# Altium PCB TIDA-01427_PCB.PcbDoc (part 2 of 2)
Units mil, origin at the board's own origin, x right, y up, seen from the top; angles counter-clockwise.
Board outline 1968.5 x 3149.61 mil, 4 copper layers (Top Layer, GND, PWR, Bottom Layer), stack 61.6 mil thick; 174 components, 73 nets, 411 pads, 102 vias.
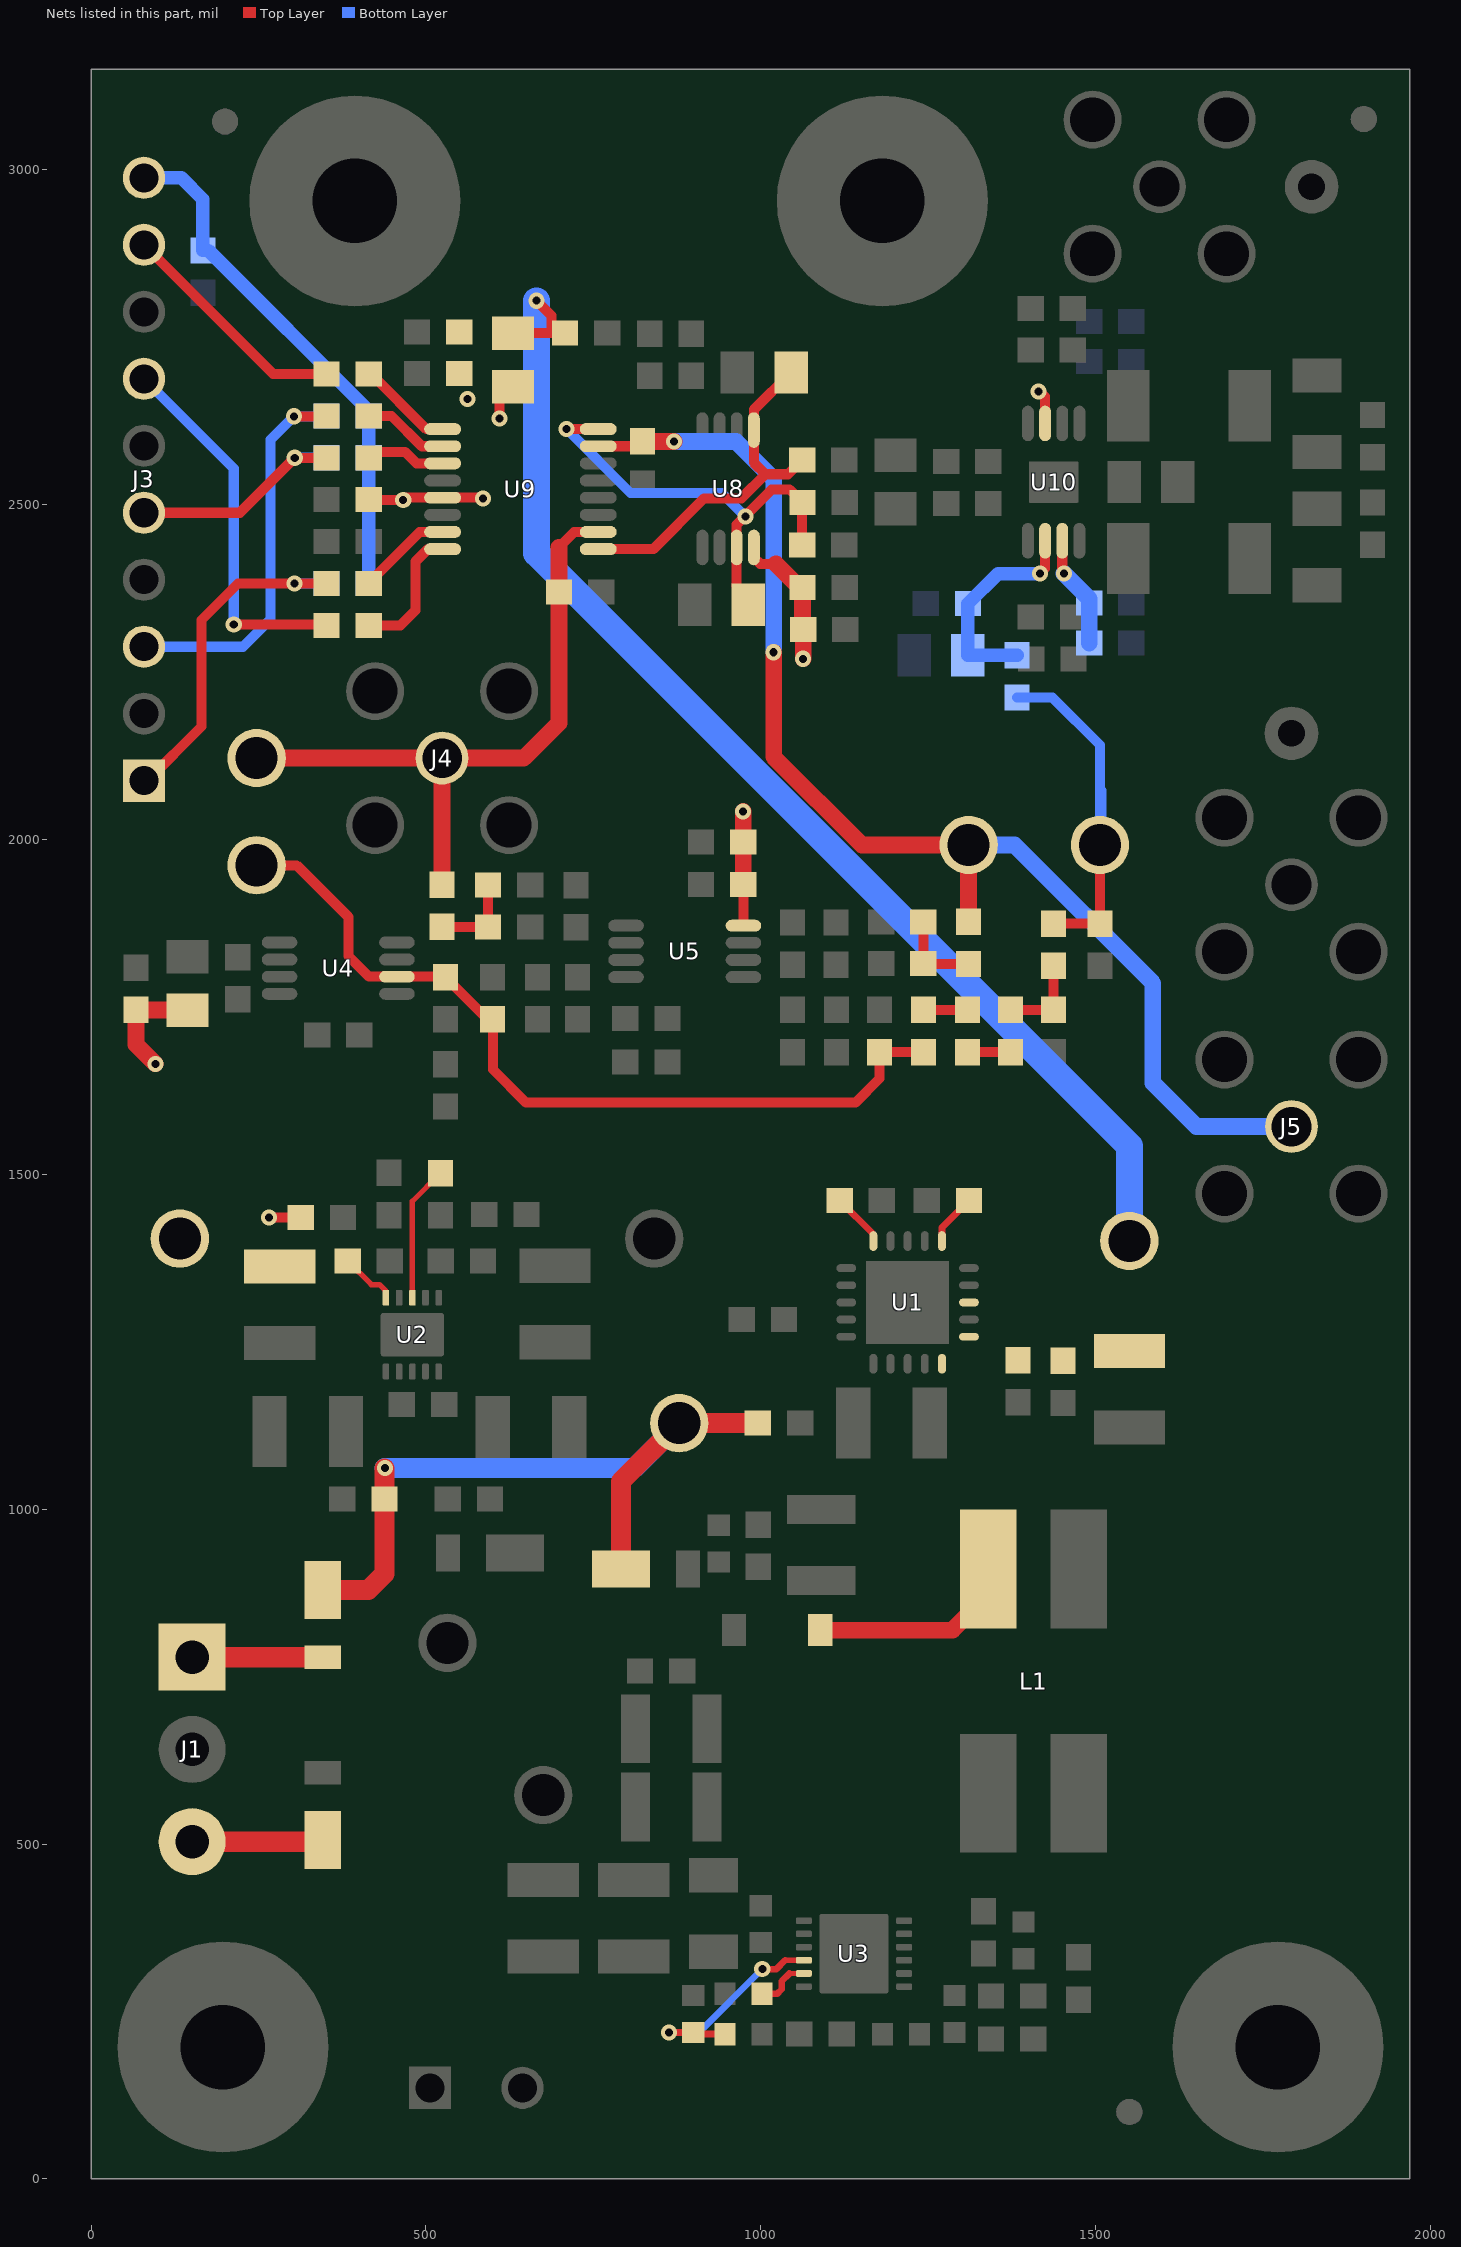
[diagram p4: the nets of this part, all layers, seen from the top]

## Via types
v1: diameter 24, hole 12, Top Layer to Bottom Layer, tented both sides, 80 vias
v2: diameter 19.68, hole 7.87, Top Layer to Bottom Layer, 19 vias
v3: diameter 24, hole 12, Top Layer to Bottom Layer, 3 vias

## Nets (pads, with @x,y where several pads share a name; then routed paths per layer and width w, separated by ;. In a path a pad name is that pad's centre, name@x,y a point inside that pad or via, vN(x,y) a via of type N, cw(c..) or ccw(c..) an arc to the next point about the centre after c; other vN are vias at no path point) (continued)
NetC76_1: C76.1 C77.1 R53.2 U10.2 | length 329.5
  Top Layer w15: v1(1416.5,2396.49) 1424.2,2404.19 U10.2@1424.2,2445.4
  Bottom Layer w20: R53.2@1382.52,2274.5 C76.1@1308.5,2274.49 1309,2274.99 C77.1@1309,2351.49 1354,2396.49 v1(1416.5,2396.49)
NetD1_2: D1.2 J1.1 | length 209.1
  Top Layer w30: J1.1@136.9,779.1 137.2,778.8 D1.2@345.9,778.8
NetD2_1: D2.1 J1.3 | length 195.9
  Top Layer w30: J1.3@151,503.41 343.5,503.41 D2.1@345.9,505.8
NetD3_2: D3.2 L1.4 | length 311
  Top Layer w25: D3.2@1088.47,819.26 1286.26,819.26 1339.38,872.38 L1.4@1339.38,910.45
NetJ3_1: J3.1 R45.1 R59.1 | length 530.7
  Top Layer w15: J3.1@84,2087.26 165,2168.26 165,2327.26 219.5,2381.76 R45.1@351.5,2381.76
  Bottom Layer w15: v1(303.43,2381.83) R59.1@351.5,2381.83
NetJ3_3: J3.3 R43.1 R58.1 | length 620.9
  Top Layer w15: v1(303,2631.26) 351,2631.26 R43.1@351.5,2631.76
  Bottom Layer w15: J3.3@79,2287.26 227,2287.26 268,2328.26 268,2596.26 v1(303,2631.26) 350.94,2631.26 R58.1@351.5,2631.83
NetJ3_5: J3.5 R40.1 R57.1 | length 354
  Top Layer w15: J3.5@79,2487.26 222,2487.26 v1(304.07,2569.33) 304.13,2569.26 R40.1@351.5,2569.26
  Bottom Layer w15: v1(304.07,2569.33) R57.1@351.5,2569.33
NetJ3_7: J3.7 R39.1 | length 562.3
  Top Layer w15: v1(213,2320.26) 348.5,2320.26 350.5,2318.26 R39.1@351.5,2319.26
  Bottom Layer w15: J3.7@79,2687.26 213,2553.26 v1(213,2320.26)
NetJ3_9: J3.9 R37.1 | length 352.4
  Top Layer w15: J3.9@79,2887.26 272,2694.26 R37.1@351.5,2694.26
NetR2_2: R2.2 U1.6 | length 77.3
  Top Layer w10: U1.6@1270.18,1399.99 1270.18,1420.31 R2.2@1310.5,1460.62
NetR3_2: R3.2 U1.10 | length 81.5
  Top Layer w10: R3.2@1117.5,1460.62 1167.82,1410.31 U1.10@1167.82,1399.99
NetR8_2: R8.2 U3.5 | length 82.3
  Top Layer w8: 1042.47,306.73 U3.5@1064.09,306.73
  Top Layer w10: R8.2@1001.46,276.26 1024,276.26 1031,283.26 1031,295.26 1042.47,306.73
NetR9_1: R9.1 R14.2 U3.4 | length 327.7
  Top Layer w8: 1036.16,326.42 U3.4@1064.09,326.42
  Top Layer w10: v1(862.44,218.7) R9.1@898.9,218.7 ; R9.1@901.34,216.26 R14.2@946.34,216.26 ; v1(1002,313.26) 1023,313.26 1036.16,326.42
  Bottom Layer w10: v1(862.44,218.7) 907.44,218.7 v1(1002,313.26)
NetR16_1: R16.1 U2.8 | length 203.4
  Top Layer w8: U2.8@479.58,1315.48 479.58,1459.5 R16.1@521.58,1501.5
NetR17_2: R17.2 R22.2 R23.1 | length 129.7
  Top Layer w15: R22.2@1242.5,1876.09 R17.2@1242.5,1814.09 1242.99,1813.6 R23.1@1310,1813.6
NetR18_2: R18.2 R20.2 R21.1 | length 131.7
  Top Layer w15: R21.1@524,1869.14 592,1869.14 R18.2@592.5,1868.64 R20.2@592.5,1931.64
NetR29_1: R29.1 R56.2 | length 64.2
  Top Layer w15: R29.1@1308.38,1682.14 R56.2@1372.62,1682.14
NetR29_2: R29.2 R54.1 | length 64.4
  Top Layer w15: R54.1@1244,1745.13 R29.2@1308.38,1745.13
NetR31_1: R31.1 R33.2 R56.1 | length 130.1
  Top Layer w15: R56.1@1372.62,1745.13 R33.2@1437,1745.13 R31.1@1437,1810.88
NetR37_2: R37.2 U9.9 | length 144.4
  Top Layer w15: R37.2@414.5,2694.26 418.35,2694.26 500.52,2612.09 U9.9@524.86,2612.09
NetR39_2: R39.2 U9.16 | length 200.2
  Top Layer w15: R39.2@414.5,2319.26 462,2319.26 484,2341.26 484,2414.26 502.7,2432.96 U9.16@524.86,2432.96
NetR40_2: R40.2 U9.11 | length 121.3
  Top Layer w15: R40.2@414.5,2569.26 423.5,2578.26 468.71,2578.26 486.06,2560.91 U9.11@524.86,2560.91
NetR43_2: R43.2 U9.10 | length 129.1
  Top Layer w15: R43.2@414.5,2631.76 448.5,2631.76 493.76,2586.5 U9.10@524.86,2586.5
NetR45_2: R45.2 U9.15 | length 142.5
  Top Layer w15: R45.2@414.5,2381.76 414.5,2382.41 490.64,2458.55 U9.15@524.86,2458.55
P5V: C2.1 C3.1 C4.1 C43.1 L4.2 P5V.1 U1.1 U1.3 U1.20 | length 1905.4
  Top Layer w15: L4.2@610,2755.26 L4.2@630,2755.26 687.5,2755.26 687.5,2781.33 v1(665.07,2803.76)
  Bottom Layer w40: v1(665.07,2803.76) 665.07,2426.93 1550,1542 P5V.1@1550,1400.26
P13V: C6.2 C7.1 C29.1 C30.1 C31.2 C56.1 C57.2 C61.1 C63.2 L2.2 P13V.1 R4.2 U2.10 U5.8 U8.8 U10.3 U10.7 | length 908.6
  Top Layer w8: R4.2@383.09,1370.36 418.45,1335 430.58,1335 440.21,1325.37 U2.10@440.21,1315.48
  Top Layer w15: L2.2@143.5,1745.14 L2.2@144,1744.64 ; v1(265.58,1435.36) C6.2@313.09,1435.36 ; C31.2@973.5,1932.64 973.86,1932.27 U5.8@973.86,1870.88 ; U8.8@989.39,2435.42 989.39,2420.61 999,2411 1022,2411 ; C57.2@1062.01,2313.76 C57.2@1063.01,2312.76 ; v1(1414.5,2668.49) 1416.5,2668.49 1424.2,2660.79 U10.7@1424.2,2620.6 ; U10.3@1449.8,2445.4 1449.8,2399.2 v1(1452.5,2396.49)
  Top Layer w25: v1(96,1664.64) 67,1693.64 C30.1@67,1745.14 L2.2@143.5,1745.14 ; C31.2@973.5,1932.64 C29.1@973.5,1995.64 v1(973.5,2041.13) ; 1022,2411 1022.31,2411 1057.55,2375.76 C56.1@1062.01,2375.76 C57.2@1062.01,2313.76 ; v1(1063.01,2269.26) C57.2@1063.01,2312.76
  Bottom Layer w25: v1(1452.5,2396.49) 1490.01,2358.99 C61.1@1490.01,2292.76
P15V_EXT: D1.1 D4.1 P15V.1 R1.2 R6.2 | length 1105.1
  Top Layer w30: D1.1@335.9,865.61 D1.1@335.9,872.5 ; D1.1@345.9,879.2 413.74,879.2 437.99,903.45 R6.2@437.99,1015 v1@437.99,1060.5 ; D4.1@790.8,910.26 790.8,1041.06 P15V.1@878,1128.26 R1.2@995.5,1128.26
  Bottom Layer w30: v1(438.5,1061) 810.74,1061 P15V.1@878,1128.26
REF_N10V_BUFFER: C72.1 J5.1 R23.2 REF_N10V_B.1 U9.7 | length 1906.5
  Top Layer w15: U9.7@757.14,2586.5 815.75,2586.5 C72.1@823,2593.76
  Top Layer w25: C72.1@823,2593.76 v1(870.5,2593.76) ; v1(1019,2279) 1019,2123 1150.62,1991.38 REF_N10V_B.1@1310,1991.38 R23.2@1310,1876.59
  Bottom Layer w25: v1(870.5,2593.76) 963,2593.76 1019,2537.76 v1(1019,2279) ; REF_N10V_B.1@1310,1991.38 1378.62,1991.38 1585,1785 1585,1636 1650,1571 J5.1@1792,1571
REF_P10V: R19.2 R24.1 R25.1 R54.2 REF_P10V.1 U4.6 | length 1270.4
  Top Layer w15: REF_P10V.1@247.2,1961.02 306.98,1961.02 384,1884 384,1825.64 414.94,1794.7 U4.6@456.6,1794.7 528.29,1794.7 R19.2@529,1793.99 600,1722.99 600,1656 649.36,1606.64 1141,1606.64 1177,1642.64 R25.1@1177,1682.14 R54.2@1242.93,1682.14
REF_P10V_BUFFER: C71.1 J4.1 R21.2 REF_P10V_B.1 U9.2 | length 992.3
  Top Layer w15: 698.5,2435.76 721.29,2458.55 U9.2@757.14,2458.55
  Top Layer w25: REF_P10V_B.1@247.2,2121.02 J4.1@523.98,2121.02 ; R21.2@524,1932.13 J4.1@524,2121 ; 698.5,2435.76 C71.1@698.5,2369.26 698.5,2173.5 646,2121 J4.1@524,2121
RFBA: C65.1 R41.1 U8.1 U9.1 | length 541.7
  Top Layer w15: U9.1@757.14,2432.96 839.31,2432.96 915.1,2508.76 970.65,2508.76 1006.65,2544.76 ; C65.1@1045,2696.76 989.39,2641.14 U8.1@989.39,2610.62 989.39,2562.02 1006.65,2544.76 ; R41.1@1061.5,2566 1040.26,2544.76 1006.65,2544.76
RFBB: C67.1 R47.1 R50.2 U8.7 U9.8 | length 693
  Top Layer w15: v1(710,2612.26) 710.17,2612.09 U9.8@757.14,2612.09 ; v1(976.99,2481.38) v1@976.99,2482.75 ; C67.1@992,2349.76 963.8,2377.96 U8.7@963.8,2435.42 963.8,2469.55 v1@976.99,2482.75 ; R50.2@1061.5,2439 1061.5,2502.25 R47.1@1062.01,2502.76 1042.88,2521.88 1016.13,2521.88 v1@976.99,2482.75
  Bottom Layer w15: v1(710,2612.26) 805.37,2516.89 941.49,2516.89 v1(976.99,2481.38)
VDD: C45.1 C58.1 C60.2 J3.10 L4.1 R34.2 R57.2 R58.2 R59.2 U9.13 | length 1001.8
  Top Layer w15: R34.2@414.5,2506.76 415,2506.26 v1(466,2506.26) 469.47,2509.73 U9.13@524.86,2509.73 583.53,2509.73 v1(585,2508.26) ; v1(610,2628.26) L4.1@610,2675.26
  Bottom Layer w20: J3.10@79,2987.26 135,2987.26 167,2955.26 C45.1@167,2878.76 175.24,2878.76 414.5,2639.5 R58.2@414.5,2631.83 R57.2@414.5,2569.33 R59.2@414.5,2381.83
  other v1: 562,2657
VOCM: C52.2 R31.2 R53.1 VOCM.1 | length 565.3
  Top Layer w15: R31.2@1437,1873.87 C52.2@1506,1873.87 VOCM.1@1506,1995.38
  Bottom Layer w15: R53.1@1382.52,2211.5 1435,2211.5 1506,2140.5 VOCM.1@1506,1995.38 ; VOCM.1@1508,1995.64 1508,2072.38
pads on no net: FID1.1 FID2.1 FID3.1 FID4.1 FID5.1 FID6.1 H1.1 H2.1 H3.1 H4.1 U1.2 U1.4 U1.5 U1.8 U1.9 U1.11 U1.12 U1.17 U1.18 U1.19 U2.11@419.35,1250.52 U2.11@419.35,1270.2 U2.11@454.78,1260.36 U2.11@504.39,1260.36 U2.11@539.82,1250.52 U2.11@539.82,1270.2 U4.1 U4.3 U4.7 U4.8

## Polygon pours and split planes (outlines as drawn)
GND on Top Layer "Bottom Layer-No Net" (solid, remove dead copper, pour order 137): 914,1019.26 914,965.26 920,959.26 922,957.26 1005,957.26 1133,957.26 1144,968.26 1145,969.26 1145,1000.26 1145,1037.26 1134,1048.26 1128,1054.26 1085,1054.26 943,1054.26 914,1025.26
GND on Top Layer "Bottom Layer-No Net" (solid, remove dead copper, pour order 136): 1160,1499.26 1160,1441.26 1161,1440.26 1163,1438.26 1186,1438.26 1223,1438.26 1229,1432.26 1238,1423.26 1238,1411.26 1238,1389.26 1239,1388.26 1240,1387.26 1246,1387.26 1249,1387.26 1251,1389.26 1251,1414.26 1251,1424.26 1268,1441.26 1268,1490.26 1268,1506.26 1256,1518.26 1255,1519.26 1182,1519.26 1172,1519.26 1160,1507.26
GND on Top Layer "Bottom Layer-No Net" (solid, remove dead copper, pour order 135): 1223,1174.26 1223,1076.26 1229,1070.26 1247,1052.26 1584,1052.26 1622,1090.26 1622,1159.26 1608,1173.26 1599.85,1181.41 1261.93,1181.41 1225.15,1181.41 1223,1179.26
P5V on Top Layer "Bottom Layer-No Net" (solid, remove dead copper, pour order 134): 1293,1293.26 1293,1238.26 1290,1235.26 1271,1235.26 1265,1235.26 1261,1231.26 1261,1204.26 1264,1201.26 1266,1199.26 1402,1199.26 1603,1199.26 1625,1221.26 1625,1431.26 1604,1452.26 1554,1452.26 1519,1452.26 1503,1436.26 1501,1434.26 1501,1360.26 1501,1349.26 1479,1327.26 1469,1317.26 1300,1317.26 1298,1317.26 1293,1312.26
NetC25_1 on Top Layer "Bottom Layer-No Net" (solid, remove dead copper, pour order 133): 513.58,1203 513.58,1192 515.58,1190 516.58,1189 522.58,1189 557.58,1189 567.58,1179 572.58,1174 572.58,1071 572.58,993.74 626.58,993.74 626.58,1039 626.58,1172 584.58,1214 580.58,1218 523.58,1218 515.58,1218 513.58,1216
NetC10_1 on Top Layer "Bottom Layer-No Net" (solid, remove dead copper, pour order 132): 353.58,1052 353.58,994.74 408.58,994.74 408.58,1019 408.58,1169 424.58,1185 428.58,1189 446.58,1189 460.58,1189 467.58,1196 467.58,1213 467.58,1214 464.58,1217 389.58,1217 353.58,1181
GND on Top Layer "Bottom Layer-No Net" (solid, remove dead copper, pour order 131): 215.58,1266 215.58,1016 234.58,997 290.58,997 302.58,1009 302.58,1161 369.58,1228 451.58,1228 611.58,1228 675.58,1164 675.58,1120 675.58,1068.42 686,1058 770.76,1058 784.58,1071.83 784.58,1258.43 767.01,1276 750.01,1293 503.58,1293 240.58,1293 215.58,1268
NetC11_2 on Top Layer "Bottom Layer-No Net" (solid, remove dead copper, pour order 130): 1202,365 1206.74,360.26 1231,360.26 1406,360.26 1412.67,366.93 1412.67,395.26 1412.67,430.59 1400,443.26 1391,452.26 1391,497.26 1391,658 1383,666 1261.74,666 1202,606.26
NetC1_1 on Top Layer "Bottom Layer-No Net" (solid, remove dead copper, pour order 122): 1037,1190.26 1037,1093.26 1042,1088.26 1060,1070.26 1147,1070.26 1162,1070.26 1168,1076.26 1175,1083.26 1175,1212.26 1175,1228.26 1169,1234.26 1148.74,1234.26 1146,1237 1146,1260 1140,1266 1076.74,1266 1037,1226.26
N13V on Top Layer "Bottom Layer-No Net" (solid, remove dead copper, pour order 121): 888.58,1440.64 888.58,1363.64 871.58,1346.64 854.58,1329.64 699.58,1329.64 574.58,1329.64 564.58,1339.64 562.58,1341.64 562.58,1386.64 569.58,1393.64 571.58,1395.64 602.58,1395.64 613.76,1395.64 624.58,1406.46 629.58,1411.46 629.58,1458 635.22,1463.64 827.58,1463.64 872.58,1463.64 888.58,1447.64
P13V on Top Layer "Bottom Layer-No Net" (solid, remove dead copper, pour order 120): 79.58,1441 79.58,1364 96.58,1347 113.58,1330 268.58,1330 393.58,1330 403.58,1340 404.58,1341 404.58,1365 404.58,1388 398.58,1394 396.58,1396 365.58,1396 354.4,1396 343.58,1406.82 336.58,1413.82 336.58,1421 336.58,1455 328.58,1463 327.58,1464 140.58,1464 95.58,1464 79.58,1448
NetC13_1 on Top Layer "Bottom Layer-No Net" (solid, remove dead copper, pour order 119): 1036.26,350 1017,369.26 895,369.26 626.26,369.26 580,323 580,146.26 580,43 598,25 704.74,25 725,45.26 725,136.26 725,206.26 755,236.26 768.8,250.06 820,250.06 957.69,250.06 971.1,263.46 971.1,289.06 971.1,314.36 993,336.26 1024.26,336.26 1030,342 1074,342 1076,344 1076,348 1074,350
NetC15_2 on Top Layer "Bottom Layer-No Net" (solid, remove dead copper, pour order 127): 586,924.26 586,830.26 604,812.26 620,796.26 845,796.26 862,779.26 862,738.26 891,709.26 891,671.26 891,415.26 900,406.26 916,390.26 985,390.26 1020,390.26 1052,358.26 1078.17,358.26 1086.92,349.51 1087.15,250.41 1078,241.26 1011,241.26 988.9,241.26 976.7,229.06 976.7,166.56 987,156.26 1000,143.26 1118,143.26 1290,143.26 1305,158.26 1309,162.26 1309,186.26 1309,236.15 1301.69,243.46 1214.8,243.46 1202,256.26 1189,269.26 1189,415.26 1148,456.26 1139,465.26 1061,465.26 1038,465.26 1014,489.26 963,540.26 963,650.26 963,750.26 857,856.26 706,856.26 680,882.26 680,908.26 680,961.26 674,967.26 593,967.26 586,960.26
NetC8_1 on Top Layer "Bottom Layer-No Net" (solid, remove dead copper, pour order 128): 871,918.26 871,866.26 935,802.26 946,791.26 980,791.26 1050.5,861.76 1104,861.76 1140.5,861.76 1149,870.26 1149,918.76 1137.24,930.51 1132.5,935.26 1128.5,939.26 912,939.26 875,939.26 871,935.26
VDD on Top Layer "Bottom Layer-No Net" (solid, remove dead copper, pour order 129): 526,2759.26 526,2668.26 533,2661.26 566,2628.26 566,2600.26 566,2494.26 576,2484.26 653,2484.26 660,2491.26 670,2501.26 670,2641.26 670,2701.26 665,2706.26 633,2706.26 602,2706.26 592,2716.26 578.27,2729.99 577.98,2771.28 571,2778.26 564.8,2784.46 552,2784.46 532.2,2784.46 526,2778.26
GND on Top Layer "Bottom Layer-No Net" (solid, remove dead copper, pour order 140): 539,92.26 539,41 523,25 468,25 423,70 423,85.26 423,433.26 578,588.26 769,779.26 839,779.26 845,773.26 845,497 864,478 864,421 858,415 617,415 539,337 539,140.26
GND on Top Layer "PWR-No Net" (solid, remove dead copper, pour order 123): 1545,2565 1398,2565 1395,2562 1395,2499.61 1396.61,2498 1542,2498 1565,2498 1568,2501 1568,2563 1566,2565
NetC66_2 on Top Layer "PWR-No Net" (solid, remove dead copper, pour order 124): 1622,2573 1762,2573 1795,2606 1873,2606 1887,2592 1931,2592 1934,2589 1940.27,2582.73 1940.27,2541.79 1940.27,2489.27 1933,2482 1886,2482 1873,2469 1871,2467 1790.56,2467 1773.6,2483.96 1764.56,2493 1605,2493 1596,2502 1596,2535 1596,2568 1601,2573
GND on Top Layer "PWR-No Net" (solid, remove dead copper, pour order 126): 1430,943 1430,488 1433,485 1453,485 1553,485 1567,499 1577,509 1577,584 1577,815 1577,968 1555,990 1545,1000 1518,1000 1433,1000 1430,997
N13V on PWR "Bottom Layer-No Net" (solid, remove dead copper, pour order 142): 682,1624 682,1405 744,1343 982,1343 1200,1561 1491,1561 1635,1705 1635,2644 1499,2780 909,2780 812,2683 812,2628.24 818,2622.24 822.24,2618 876,2618 1255,2618 1335,2698 1429,2698 1442,2685 1442,2623 1504,2561 1504,2182 1428,2106 1164,2106
P13V on PWR "Bottom Layer-No Net" (solid, remove dead copper, pour order 141): 62,1765 62,1384 105,1341 372,1341 421,1390 421,1644 485,1708 697,1708 1155,2166 1384,2166 1426,2166 1447,2187 1470,2210 1470,2424 1399.46,2494.54 1390,2504 1390,2561 1427,2598 1427,2675 1421,2681 1361,2681 568,1888 185,1888
GND on GND "Bottom Layer-No Net" (solid, remove dead copper, pour order 139): 0,493 104,389 282,389 382,289 382,78 460,0 1488,0 1587,99 1587,278 1698,389 1895,389 1968.5,462.5 1968.5,2694.5 1968.5,3069.5 1888.39,3149.61 1433.61,3149.61 1370.5,3086.5 1370.5,2849.5 1282,2761 1096,2761 996,2861 996,3092 938.39,3149.61 646.61,3149.61 578.03,3081.03 578.03,2861.03 489,2772 303,2772 211,2864 211,3094 155.39,3149.61 84.35,3149.61 0,3065.26
VDD on Bottom Layer "PWR-No Net" (solid, remove dead copper, pour order 125): 389,2645 389,2366 397,2358 562,2358 591,2387 634.81,2430.81 634.81,2524.12 634.81,2649.19 614,2670 399,2670 389,2660 389,2658
GND on Bottom Layer "Bottom Layer-No Net" (solid, remove dead copper, pour order 138): 0,493 104,389 282,389 382,289 382,78 460,0 1488,0 1587,99 1587,278 1698,389 1895,389 1968.5,462.5 1968.5,2694.5 1968.5,3069.5 1888.39,3149.61 1433.61,3149.61 1370.5,3086.5 1370.5,2849.5 1282,2761 1096,2761 996,2861 996,3092 938.39,3149.61 646.61,3149.61 578.03,3081.03 578.03,2861.03 489,2772 303,2772 211,2864 211,3094 155.39,3149.61 84.35,3149.61 0,3065.26

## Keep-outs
Keep-Out Layer:
  lines w10: 10,10 1958.5,10 1958.5,3139.61 10,3139.61 10,10

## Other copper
Top Layer:
  text ".Layer_Name" at 577,-937.23 h60
GND:
  pour cut-out: 521,266 521,632.26 732,843.26 868,843.26 909,884.26 909,1020.26 945,1056.26 1126,1056.26 1163,1019.26 1909.74,1019.26 1968.51,960.49 1968.51,1107.51 1909.26,1048.26 1180,1048.26 1142,1086.26 926,1086.26 882,1042.26 882,907.26 853,878.26 718,878.26 489,649.26 489,266 496.5,258.5 513.5,258.5
  text ".Layer_Name" at 580,-941.74 h60
PWR:
  text ".Layer_Name" at 580,-936.74 h60
Bottom Layer:
  pour cut-out: 521,266 521,632.26 732,843.26 868,843.26 909,884.26 909,1020.26 945,1056.26 1126,1056.26 1163,1019.26 1909.74,1019.26 1968.51,960.49 1968.51,1107.51 1909.26,1048.26 1180,1048.26 1142,1086.26 926,1086.26 882,1042.26 882,907.26 853,878.26 718,878.26 489,649.26 489,266 496.5,258.5 513.5,258.5
  text ".Layer_Name" at 577,-937.23 h60

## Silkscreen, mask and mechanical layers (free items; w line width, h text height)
Top Overlay:
  lines w6: 157.74,2161 157.74,2142.26 165,2135 ; 277,2328 295,2310 309,2310 ; 321,1920 334,1920 346,1932 346,1939 ; 352.9,660 334.9,642 306.9,642 ; 442,2783 257,2783 187,2713 187,2594 187,2306 213,2280 981,2280 1032,2229 1853,2229 1916,2292 ; 499,2640.26 506,2640.26 518,2652.26 ; 539,2844 559,2864 985,2864 1002,2864 1086,2780 1255,2780 ; 681,1970 681,2025 689,2033 ; 767,1957 790,1957 807,1974 807,1982 ; 1006,432.26 1006,436.26 1015,445.26 ; 1010,126.26 1010,185.26 ; 1097,2601 1097,2666 1100,2669 ; 1164,2379 1194,2379 ; 1164.14,2315.14 1194.14,2315.14 ; 1165,2414 1178,2414 ; 1221.99,1961.99 1231,1952.97 1231,1915 ; 1334,169 1334,121 1352,103 ; 1512,2806 1876,2806 1912,2770 ; 306.9,642 314.9,650 314.9,634 306.9,642
  text "+15V" at 128.9,877 h40
  text "GND" at 314.9,678 h40
  text "TIDA-01427-E2" at 1832,470 h120 r90
  text "-15V" at 111.9,377 h40
  text "GND" at 314,33 h40
  text "+5V" at 731,33 h40
  text ".Layer_Name" at 577,-937.23 h60
Bottom Overlay:
  text ".Layer_Name" at 577,-937.23 h60
Top Paste:
  text ".Layer_Name" at 577,-937.23 h60
Bottom Paste:
  text ".Layer_Name" at 577,-937.23 h60
Top Solder:
  text ".Layer_Name" at 577,-937.23 h60
  text ".Layer_Name" at 577,-937.23 h60
Bottom Solder:
  text ".Layer_Name" at 577,-937.23 h60
Drill Guide:
  text ".Layer_Name" at 577,-937.23 h60
M1 Board Outline:
  the board outline again, w10
M2 Board Dimensions:
  rectangle: 0,-353.74 125,-228.74
  rectangle: 125,-478.74 500,-353.74
  lines w7: 0,-353.74 1000,-353.74 ; 125,-478.74 125,-228.74 ; 250,-478.74 250,-228.74 ; 500,-478.74 500,-228.74 ; 750,-478.74 750,-228.74 ; 0,-478.74 1000,-478.74 1000,-228.74 0,-228.74 0,-478.74
M3 3D STEP Top:
  text ".Layer_Name" at 577,-937.23 h60
M4 3D STEP Bottom:
  text ".Layer_Name" at 577,-937.23 h60
M5 Assembly Top:
  circle w10: c137,779 r9.81
  circle w10: c506.1,56.26 r11.04
  circle w10: c79,2087.26 r9.85
  lines w10: -292,-1008.91 6308,-1008.91 ; -292,-805.57 6310,-805.57 ; -292,-602.24 -292,-1212.24 3713,-1212.24 6310,-1212.24 6310,-602.24 -291.5,-602.24 -291.5,-1212.24 1284,-1212.24 ; 2173,-1212.24 2173,-602.24 ; 3440,-805.57 3440,-602.24 ; 4280,-805.57 4280,-602.24 ; 4902,-1218.74 4902,-1015.91
  text "COMPONENTS MARKED 'DNP' SHOULD NOT BE POPULATED." at 1153.5,-397.24 h60
  text "ASSEMBLY VARIANT:" at 1153,-512.74 h60
  text ".VariantName" at 2189,-512.74 h60
  text "PCB VIEWED FROM TOP SIDE" at -228.5,-734.41 h60
  text "BOARD #:" at 2248,-734.41 h60
  text ".PRJ_Number" at 2793.5,-734.41 h60
  text "REV:" at 3638,-734.41 h60
  text ".PCB_Rev" at 3929.5,-734.41 h60
  text "SVN REV:" at 4476,-734.41 h60
  text ".VersionControl_RevNumber" at 4982,-734.41 h60
  text ".Layer_Name" at 583,-936.74 h60
  text "LAYER NAME =" at -229,-937.74 h60
  text "TID #:" at 2248,-937.74 h60
  text ".TID" at 2793.5,-937.74 h60
  text "PLOT NAME =" at -228.5,-1143.08 h60
  text ".plot_File_Name" at 577,-1143.08 h60
  text "GENERATED    :" at 2250,-1143.08 h60
  text ".Print_Date" at 3119.5,-1143.08 h60
  text ".Print_Time" at 3848.5,-1143.08 h60
  text "TEXAS INSTRUMENTS" at 5113,-1143.08 h60
M6 Assembly Bottom:
  lines w10: -292.5,-806.07 6309.5,-806.07 ; -290.5,-1009.41 6309.5,-1009.41 ; 1115.5,-1219.24 1115.5,-1016.41 ; 1737.5,-806.07 1737.5,-602.74 ; 2577.5,-806.07 2577.5,-602.74 ; 3844.5,-1212.74 3844.5,-602.74 ; 4733.5,-1212.74 6309,-1212.74 6309,-602.74 -292.5,-602.74 -292.5,-1212.74 2304.5,-1212.74 6309.5,-1212.74 6309.5,-602.74
  text "COMPONENTS MARKED 'DNP' SHOULD NOT BE POPULATED." at 6102,-396.74 h60
  text ".VariantName" at 5058,-512.74 h60
  text "ASSEMBLY VARIANT:" at 6097,-512.74 h60
  text ".VersionControl_RevNumber" at 1035.5,-734.91 h60
  text "SVN REV:" at 1541.5,-734.91 h60
  text ".PCB_Rev" at 2088,-734.91 h60
  text "REV:" at 2379.5,-734.91 h60
  text ".PRJ_Number" at 3224,-734.91 h60
  text "BOARD #:" at 3769.5,-734.91 h60
  text "PCB VIEWED FROM BOTTOM SIDE" at 6246,-734.91 h60
  text ".Layer_Name" at 5352,-936.74 h60
  text ".TID" at 3224,-938.24 h60
  text "TID #:" at 3769.5,-938.24 h60
  text "LAYER NAME =" at 6199,-942.74 h60
  text "TEXAS INSTRUMENTS" at 904.5,-1143.58 h60
  text ".Print_Time" at 2169,-1143.58 h60
  text ".Print_Date" at 2898,-1143.58 h60
  text "GENERATED    :" at 3767.5,-1143.58 h60
  text ".plot_File_Name" at 5440.5,-1143.58 h60
  text "PLOT NAME =" at 6246,-1143.58 h60
M9 Title Sheet:
  drawing of 57 lines, arcs and shapes, not listed
  text "1" at 739.84,7957.76 h70
  text "2" at 3235.5,7957.76 h70
  text "3" at 5724.84,7957.76 h70
  text "4" at 8231.51,7957.76 h70
  text "5" at 10730.5,7957.76 h70
  text "6" at 13235.5,7957.76 h70
  text "A" at -416.5,6814.76 h70
  text "A" at 14383.5,6814.76 h70
  text "B" at -416.5,4434.76 h70
  text "B" at 14383.5,4434.76 h70
  text "C" at -416.5,2059.76 h70
  text "C" at 14383.5,2059.76 h70
  text "PROJECT TITLE:" at 11343.5,198.76 h45
  text ".PRJ_Title" at 11393.5,65.43 h70
  text "DESIGNED FOR:" at 11343.5,-102.24 h45
  text ".PRJ_Customer" at 11393.5,-242.24 h70
  text "D" at -416.5,-310.24 h70
  text "D" at 14383.5,-310.24 h70
  text "FILE NAME:" at 11343.5,-402.24 h45
  text ".PCB_File_Name_No_Path" at 11393.5,-522.24 h70
  text "Texas Instruments (TI) and/or its licensors do not warrant the accuracy or completeness of this specification" at 6374,-684.08 h45
  text "ENGINEER:" at 11343.5,-692.24 h45
  text "LAYOUT BY:" at 12848.5,-692.24 h45
  text "or any information contained therein. TI and/or its licensors do not warrant that this design will meet" at 6329.01,-796.74 h45
  text ".PRJ_Engineer" at 11393.5,-847.23 h70
  text ".PCB_Layout" at 12899,-847.23 h70
  text "the specifications, will be suitable for your application or fit for any particular purpose, or will operate in" at 6329.01,-909.41 h45
  text "ALTIUM DESIGNER VERSION:" at 12848.5,-1002.24 h45
  text "an implementation. TI and/or its licensors do not warrant that the design is production worthy. You should" at 6329.01,-1022.07 h45
  text "completely validate and test your design implementation to confirm the system functionality for your application." at 6374,-1134.74 h45
  text ".print_Scale" at 11393.5,-1135.57 h70
  text ".Application_BuildNumber" at 12899,-1135.57 h70
  text "1" at 739.84,-1342.24 h70
  text "2" at 3235.5,-1342.24 h70
  text "3" at 5724.84,-1342.24 h70
  text "4" at 8231.51,-1342.24 h70
  text "5" at 10730.5,-1342.24 h70
  text "6" at 13235.5,-1342.24 h70
M10 Fab Notes:
  drawing of 173 lines, arcs and shapes, not listed
  text "DESIGN INFORMATION" at 12378.02,6122.26 h60
  text "MIN. TRACK WIDTH:" at 11733.46,5942.26 h60
  text "8" at 12829.7,5942.26 h60
  text "MIL" at 12984.46,5942.26 h60
  text "MIN. CLEARANCE:" at 11733.46,5810.26 h60
  text "0.2" at 12769.7,5810.26 h60
  text "mm" at 12984.46,5810.26 h60
  text "MIN. VIA PAD SIZE:" at 11733.46,5678.26 h60
  text "19.69" at 12690,5678.26 h60
  text "MIL" at 12984.46,5678.26 h60
  text "0.15mm (5.91MIL)" at 12428.46,5536.55 h60
  text "MINIMUM ANNULAR RING" at 11404.23,5532.26 h60
  text "EXTERNAL" at 13186,5532.26 h60
  text "PER" at 11604.23,5414.26 h60
  text "IPC-D-275 CLASS 2 LEVEL C" at 11824.23,5414.26 h60
  text "MIL, HOLES" at 13312.46,5301.97 h60
  text "+/-" at 12920,5301.26 h60
  text "+/-" at 13774,5301.26 h60
  text "REGISTRATION TOLERANCES:" at 11404.23,5296.26 h60
  text "METAL" at 12604,5296.26 h60
  text "5" at 13180.2,5296.26 h60
  text "3" at 14013.2,5296.26 h60
  text "MIL" at 14129.46,5296.26 h60
  text "+/-" at 13774,5183.26 h60
  text "HOLE SIZE TOLERANCE (UNLESS OTHERWISE SPECIFIED):" at 11404.23,5178.26 h60
  text "3" at 14013.2,5178.26 h60
  text "MIL" at 14129.46,5178.26 h60
  text "MATERIAL:" at 11329.46,4968.8 h60
  text "FR-4 High Tg" at 12315.9,4828.47 h60
  text "FR-408" at 11750.46,4819.9 h60
  text "OTHER" at 13238.46,4819.9 h60
  text "X" at 12161,4816.26 h60
  text "63 MIL (1.6mm) +/-10%" at 12070.56,4657.18 h60
  text "THICKNESS:" at 11404.23,4652.9 h60
  text "X" at 11942.4,4652.9 h60
  text "OTHER" at 13355.46,4652.9 h60
  text "TOLERANCE:" at 11404.23,4494.9 h60
  text "X" at 12243.53,4494.9 h60
  text "ANSI IPC-6012 TYPE 3 CLASS 2" at 12430.48,4494.9 h60
  text "OTHER +/-" at 12430.46,4338.9 h60
  text "BOW & TWIST:" at 11404.23,4181.9 h60
  text "X" at 12243.53,4181.9 h60
  text "ANSI IPC-6012 TYPE 3 CLASS 2" at 12430.48,4181.9 h60
  text "OTHER +/-" at 12430.46,4023.39 h60
  text "DRILLING:" at 11329.46,3884.9 h60
  text "REFERENCE:" at 11404.23,3767.9 h60
  text "X" at 12052.46,3767.9 h60
  text "AS SHOWN" at 12239.46,3767.9 h60
  text "X" at 12953.46,3767.9 h60
  text "NC_DRILL FILES" at 13090.46,3767.9 h60
  text "PTH COPPER THICKNESS:" at 11404.23,3609.9 h60
  text "X" at 12534.46,3609.9 h60
  text "20-30 um" at 12671.46,3609.9 h60
  text "OTHER" at 13388.46,3609.9 h60
  text "BOARD FINISH:" at 11329.46,3450.9 h60
  text "SILKSCREEN:" at 11484.68,3332.9 h60
  text "X" at 12433.46,3332.9 h60
  text "TOP" at 12559.46,3332.9 h60
  text "X" at 12943.46,3332.9 h60
  text "BOTTOM" at 13070.46,3332.9 h60
  text "SILKSCREEN COLOR:" at 11484.68,3165.9 h60
  text "X" at 12432.42,3165.9 h60
  text "WHITE" at 12559.46,3165.9 h60
  text "OTHER" at 13070.46,3165.9 h60
  text "X" at 12563.42,3006.7 h60
  text "GREEN" at 12690.46,3006.7 h60
  text "OTHER" at 13308.46,3006.7 h60
  text "SOLDER RESIST COLOR:" at 11484.68,2995.9 h60
  text "X" at 12563.42,2836.7 h60
  text "MATTE" at 12690.46,2836.7 h60
  text "SEMI-GLOSS" at 13308,2836.06 h60
  text "IMMERSION GOLD (ENIG)" at 12390.46,2648.18 h60
  text "ENEPIG" at 13728,2644.9 h60
  text "SURFACE FINISH:" at 11329.46,2643.9 h60
  text "X" at 12203.51,2643.9 h60
  text "IMM. TIN/SILVER OR EQUIV" at 11659,2486.9 h60
  text "OTHER" at 13090.46,2486.9 h60
  text "ARRAY/PANEL:" at 11329.46,2307.9 h60
  text "CUT AND TRIM PER M1 BOARD OUTLINE" at 12390.46,2303.61 h60
  text "N.C. ROUTE" at 12390.46,2151.9 h60
  text "X" at 13069.46,2151.9 h60
  text "V. SCORE" at 13256.46,2151.9 h60
  text "CERTIFICATION:" at 11329.46,2014.9 h60
  text "MATERIALS AND WORKMANSHIP FOR ALL PCBS" at 12054.46,2014.9 h60
  text "TO MEET OR EXCEED THE REQUIREMENTS OF:" at 12054.46,1916.9 h60
  text "X" at 11680.96,1780.39 h60
  text "ANSI IPC-A-600F CLASS ->" at 11819.96,1780.39 h60
  text "X" at 13459.02,1780.39 h60
  text "2" at 13577.96,1780.39 h60
  text "1" at 13262.96,1778.9 h60
  text "3" at 13931.96,1778.9 h60
  text "X" at 12495.02,1620.9 h60
  text "RoHS" at 12631.96,1620.9 h60
  text "OTHER" at 13276.36,1620.9 h60
  text "PER ORDER" at 13673.42,1620.9 h60
  text "ALL BOARDS MUST MEET OR EXCEED UL94-V0 REQUIREMENTS." at 11357,1455.26 h60
  text "PCB MUST BEAR THE UL94V-0 UL REGISTERED MATERIAL ID NUMBER" at 11357,1335.26 h60
  text "ADDITIONAL REQUIREMENTS:" at 11329.46,1161.9 h60
  text "MICROSECTION:" at 11404.23,1046.9 h60
  text "YES" at 12309.96,1046.9 h60
  text "REQUIRED" at 13171.46,890.75 h60
  text "BARE BOARD ELEC. TEST:" at 11404.23,887.9 h60
  text "NONE" at 12709.96,887.9 h60
  text "X" at 13044.46,887.9 h60
  text "PER ORDER" at 13763.46,887.9 h60
M11 Gerber Information:
  lines w10: -292,-1008.91 6308,-1008.91 ; -292,-805.57 6310,-805.57 ; -292,-602.24 -292,-1212.24 3713,-1212.24 6310,-1212.24 6310,-602.24 -291.5,-602.24 -291.5,-1212.24 1284,-1212.24 ; 2173,-1212.24 2173,-602.24 ; 3440,-805.57 3440,-602.24 ; 4280,-805.57 4280,-602.24 ; 4902,-1218.74 4902,-1015.91
  text "ALL ARTWORK VIEWED FROM TOP SIDE" at -228.5,-734.41 h60
  text "BOARD #:" at 2248,-734.41 h60
  text ".PRJ_Number" at 2793.5,-734.41 h60
  text "REV:" at 3638,-734.41 h60
  text ".PCB_Rev" at 3929.5,-734.41 h60
  text "SVN REV:" at 4476,-734.41 h60
  text ".VersionControl_RevNumber" at 4982,-734.41 h60
  text "LAYER NAME =" at -228.5,-937.23 h60
  text "TID #:" at 2248,-937.74 h60
  text ".TID" at 2793.5,-937.74 h60
  text "PLOT NAME =" at -228.5,-1143.08 h60
  text ".plot_File_Name" at 577,-1143.08 h60
  text "GENERATED    :" at 2250,-1143.08 h60
  text ".Print_Date" at 3119.5,-1143.08 h60
  text ".Print_Time" at 3848.5,-1143.08 h60
  text "TEXAS INSTRUMENTS" at 5113,-1143.08 h60
M12 Stackup:
  drawing of 295 lines, arcs and shapes, not listed
  text "Layer" at 9713.5,7703.76 h60
  text "Name" at 10123.41,7703.76 h60
  text "Material" at 11053.16,7703.76 h60
  text "Thickness" at 11912.92,7703.76 h60
  text "Constant" at 12562.76,7703.76 h60
  text "Board Layer Stack" at 13132.62,7703.76 h60
  text "1" at 9713.5,7583.76 h60
  text "Top Overlay" at 10123.41,7583.76 h60
  text "2" at 9713.5,7463.76 h60
  text "Top Solder" at 10123.41,7463.76 h60
  text "Solder Resist" at 11053.16,7463.76 h60
  text "0.40mil" at 11912.92,7463.76 h60
  text "3.5" at 12562.76,7463.76 h60
  text "3" at 9713.5,7343.76 h60
  text "Top Layer" at 10123.41,7343.76 h60
  text "Copper" at 11053.16,7343.76 h60
  text "1.40mil" at 11912.92,7343.76 h60
  text "4" at 9713.5,7223.76 h60
  text "Dielectric 1" at 10123.41,7223.76 h60
  text "FR-4 High Tg" at 11053.16,7223.76 h60
  text "10.00mil" at 11912.92,7223.76 h60
  text "4.2" at 12562.76,7223.76 h60
  text "5" at 9713.5,7103.76 h60
  text "GND" at 10123.41,7103.76 h60
  text "Copper" at 11053.16,7103.76 h60
  text "1.40mil" at 11912.92,7103.76 h60
  text "6" at 9713.5,6983.76 h60
  text "Dielectric 2" at 10123.41,6983.76 h60
  text "FR-4 High Tg" at 11053.16,6983.76 h60
  text "36.00mil" at 11912.92,6983.76 h60
  text "4.2" at 12562.76,6983.76 h60
  text "7" at 9713.5,6863.76 h60
  text "PWR" at 10123.41,6863.76 h60
  text "Copper" at 11053.16,6863.76 h60
  text "1.40mil" at 11912.92,6863.76 h60
  text "8" at 9713.5,6743.76 h60
  text "Dielectric3" at 10123.41,6743.76 h60
  text "FR-4 High Tg" at 11053.16,6743.76 h60
  text "10.00mil" at 11912.92,6743.76 h60
  text "4.8" at 12562.76,6743.76 h60
  text "9" at 9713.5,6623.76 h60
  text "Bottom Layer" at 10123.41,6623.76 h60
  text "Copper" at 11053.16,6623.76 h60
  text "1.40mil" at 11912.92,6623.76 h60
  text "10" at 9713.5,6503.76 h60
  text "Bottom Solder" at 10123.41,6503.76 h60
  text "Solder Resist" at 11053.16,6503.76 h60
  text "0.40mil" at 11912.92,6503.76 h60
  text "3.5" at 12562.76,6503.76 h60
  text "11" at 9713.5,6383.76 h60
  text "Bottom Overlay" at 10123.41,6383.76 h60
M13 Component Bodies Top:
  text ".Layer_Name" at 577,-937.23 h60
M14 Component Bodies Bottom:
  text ".Layer_Name" at 577,-937.23 h60
M15 Courtyards Top:
  text ".Layer_Name" at 577,-937.23 h60
M16 Courtyards Bottom:
  text ".Layer_Name" at 577,-937.23 h60
Drill Drawing:
  circle w10: c2722.25,1982.59 r33.33
  lines w10: 2688.92,1049.26 2688.92,1065.93 2705.58,1082.59 2688.92,1099.26 2688.92,1115.93 2705.58,1115.93 2722.25,1099.26 2738.92,1115.93 2755.58,1115.93 2755.58,1099.26 2738.92,1082.59 2755.58,1065.93 2755.58,1049.26 2738.92,1049.26 2722.25,1065.93 2705.58,1049.26 2688.92,1049.26 ; 2688.92,1232.59 2722.25,1199.26 2755.58,1232.59 2722.25,1265.93 2688.92,1232.59 ; 2688.92,1349.26 2755.58,1349.26 2755.58,1415.93 2688.92,1415.93 2688.92,1349.26 ; 2688.92,1499.26 2722.25,1515.93 2755.58,1499.26 2738.92,1532.59 2755.58,1565.93 2722.25,1549.26 2688.92,1565.93 2705.58,1532.59 2688.92,1499.26 ; 2688.92,1715.93 2755.58,1715.93 2722.25,1649.26 2688.92,1715.93 ; 2688.92,1815.93 2705.58,1815.93 2722.25,1799.26 2738.92,1815.93 2755.58,1815.93 2738.92,1832.59 2755.58,1849.26 2738.92,1849.26 2722.25,1865.93 2705.58,1849.26 2688.92,1849.26 2705.58,1832.59 2688.92,1815.93 ; 2688.92,2265.93 2705.58,2265.93 2705.58,2249.26 2738.92,2249.26 2738.92,2265.93 2755.58,2265.93 2755.58,2299.26 2738.92,2299.26 2738.92,2315.93 2705.58,2315.93 2705.58,2299.26 2688.92,2299.26 2688.92,2265.93
  lines w15: 2629.12,1004.26 7703.74,1004.26 ; 2629.12,2354.26 7703.74,2354.26 ; 3180,854.26 3180,2504.26 ; 3769.84,854.26 3769.84,2504.26 ; 4919.51,854.26 4919.51,2504.26 ; 5425.38,854.26 5425.38,2504.26 ; 6159.19,854.26 6159.19,2504.26 ; 2629.12,854.26 7703.74,854.26 7703.74,2504.26 2629.12,2504.26 2629.12,854.26
  text "Symbol" at 2719.12,2399.26 h72
  text "Count" at 3225,2399.26 h72
  text "Hole Size" at 3814.84,2399.26 h72
  text "Plated" at 4964.51,2399.26 h72
  text "Hole Type" at 5470.38,2399.26 h72
  text "Drill Layer Pair" at 6204.19,2399.26 h72
  text "2" at 3225,2249.26 h60
  text "40.00mil (1.016mm)" at 3814.84,2249.26 h60
  text "PTH" at 4964.51,2249.26 h60
  text "Round" at 5470.38,2249.26 h60
  text "Top Layer - Bottom Layer" at 6204.19,2249.26 h60
  text "3" at 3225,2099.26 h60
  text "50.00mil (1.270mm)" at 3814.84,2099.26 h60
  text "PTH" at 4964.51,2099.26 h60
  text "Round" at 5470.38,2099.26 h60
  text "Top Layer - Bottom Layer" at 6204.19,2099.26 h60
  text "B" at 2690.03,2089.27 h66.67
  text "4" at 3225,1949.26 h60
  text "59.06mil (1.500mm)" at 3814.84,1949.26 h60
  text "PTH" at 4964.51,1949.26 h60
  text "Round" at 5470.38,1949.26 h60
  text "Top Layer - Bottom Layer" at 6204.19,1949.26 h60
  text "4" at 3225,1799.26 h60
  text "125.98mil (3.200mm)" at 3814.84,1799.26 h60
  text "PTH" at 4964.51,1799.26 h60
  text "Round" at 5470.38,1799.26 h60
  text "Top Layer - Bottom Layer" at 6204.19,1799.26 h60
  text "10" at 3225,1649.26 h60
  text "63.00mil (1.600mm)" at 3814.84,1649.26 h60
  text "PTH" at 4964.51,1649.26 h60
  text "Round" at 5470.38,1649.26 h60
  text "Top Layer - Bottom Layer" at 6204.19,1649.26 h60
  text "12" at 3225,1499.26 h60
  text "43.31mil (1.100mm)" at 3814.84,1499.26 h60
  text "PTH" at 4964.51,1499.26 h60
  text "Round" at 5470.38,1499.26 h60
  text "Top Layer - Bottom Layer" at 6204.19,1499.26 h60
  text "16" at 3225,1349.26 h60
  text "66.93mil (1.700mm)" at 3814.84,1349.26 h60
  text "PTH" at 4964.51,1349.26 h60
  text "Round" at 5470.38,1349.26 h60
  text "Top Layer - Bottom Layer" at 6204.19,1349.26 h60
  text "19" at 3225,1199.26 h60
  text "7.87mil (0.200mm)" at 3814.84,1199.26 h60
  text "PTH" at 4964.51,1199.26 h60
  text "Round" at 5470.38,1199.26 h60
  text "Top Layer - Bottom Layer" at 6204.19,1199.26 h60
  text "83" at 3225,1049.26 h60
  text "12.00mil (0.305mm)" at 3814.84,1049.26 h60
  text "PTH" at 4964.51,1049.26 h60
  text "Round" at 5470.38,1049.26 h60
  text "Top Layer - Bottom Layer" at 6204.19,1049.26 h60
  text "153 Total" at 3225,899.26 h60
  text "DRILL TABLE" at 3101,683.26 h60
  text "FOR 7.874MIL DRILL +0/-7.874MIL" at 3101,574.26 h60
  text "FOR 12MIL DRILL +0/-12MIL" at 3099,476.26 h60
  text "FOR PTH DRILL +/-3MIL" at 3099,368.26 h60
  text "NOTE:" at 3097,250.26 h60
  text "12MIL Vias are Tented in both the sides." at 3096,159.26 h60
  text "7.874MIL vias are not Tented." at 3098,61.26 h60
  text "This is not an Impedance controlled board." at 3094,-125.74 h60
  text ".Layer_Name" at 577,-937.23 h60
M17 Embedded Cavity:
  text ".Layer_Name" at 577,-937.23 h60
M18 Embedded Assembly:
  text ".Layer_Name" at 577,-937.23 h60
M19 Embedded Keepout:
  text ".Layer_Name" at 577,-937.23 h60

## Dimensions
0,0 to 0,3149.61 on M2 Board Dimensions
0,-478.74 to 1000,-478.74 on M2 Board Dimensions
0,0 to 1968.5,0 on M2 Board Dimensions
